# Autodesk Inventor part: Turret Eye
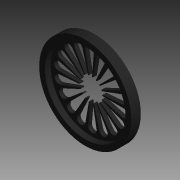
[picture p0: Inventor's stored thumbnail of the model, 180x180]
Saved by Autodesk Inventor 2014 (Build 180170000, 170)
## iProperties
Created: 2013-09
Part Number: Turret Eye
Material: Generic
Document SubType Name: Modeling
Designer: Joey Mason
Appearance: Black
Author: Joey Mason
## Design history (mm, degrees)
sketch "Sketch10"
  geometry: L1 (7.62, 0)-(21.577, 0); L2 (7.36, -1.972)-(20.854, -5.588); L3 (7.16, 2.606)-(20.276, 7.38); L4 (7.591, 0.664)-(21.508, 1.882); L5 (5.837, 4.898)-(16.529, 13.87); L6 (6.906, 3.22)-(19.567, 9.124); L7 (3.81, 6.599)-(10.789, 18.687); L8 (5.388, 5.388)-(15.266, 15.266); L9 (1.323, 7.504)-(3.747, 21.25); L10 (3.22, 6.906)-(9.124, 19.567); L11 (-1.323, 7.504)-(-3.747, 21.25); L12 (0.664, 7.591)-(1.882, 21.508); L13 (-3.81, 6.599)-(-10.789, 18.687); L14 (-1.972, 7.36)-(-5.588, 20.854); L15 (-5.837, 4.898)-(-16.529, 13.87); L16 (-4.371, 6.242)-(-12.384, 17.685); L17 (-7.16, 2.606)-(-20.276, 7.38); L18 (-6.242, 4.371)-(-17.685, 12.384); L19 (-7.62, 0)-(-21.577, 0); L20 (-7.36, 1.972)-(-20.854, 5.588); L21 (-7.16, -2.606)-(-20.276, -7.38); L22 (-7.591, -0.664)-(-21.508, -1.882); L23 (-5.837, -4.898)-(-16.529, -13.87); L24 (-6.906, -3.22)-(-19.567, -9.124); L25 (-3.81, -6.599)-(-10.789, -18.687); L26 (-5.388, -5.388)-(-15.266, -15.266); L27 (-1.323, -7.504)-(-3.747, -21.25); L28 (-3.22, -6.906)-(-9.124, -19.567); L29 (1.323, -7.504)-(3.747, -21.25); L30 (-0.664, -7.591)-(-1.882, -21.508); L31 (3.81, -6.599)-(10.789, -18.687); L32 (1.972, -7.36)-(5.588, -20.854); L33 (5.837, -4.898)-(16.529, -13.87); L34 (4.371, -6.242)-(12.384, -17.685); L35 (7.16, -2.606)-(20.276, -7.38); L36 (6.242, -4.371)-(17.685, -12.384); C1 r 30.48 at (0, 0); C2 r 26.67 at (0, 0); A1 r 2.841 centre (21.577, -2.841) between (20.854, -5.588) and (21.577, 0); A2 r 2.841 centre (21.248, 4.711) between (21.508, 1.882) and (20.276, 7.38); A3 r 2.841 centre (18.355, 11.694) between (19.567, 9.124) and (16.529, 13.87); A4 r 2.841 centre (13.249, 17.266) between (15.266, 15.266) and (10.789, 18.687); A5 r 2.841 centre (6.544, 20.756) between (9.124, 19.567) and (3.747, 21.25); A6 r 2.841 centre (-0.949, 21.743) between (1.882, 21.508) and (-3.747, 21.25); A7 r 2.841 centre (-8.329, 20.107) between (-5.588, 20.854) and (-10.789, 18.687); A8 r 2.841 centre (-14.703, 16.046) between (-12.384, 17.685) and (-16.529, 13.87); A9 r 2.841 centre (-19.305, 10.049) between (-17.685, 12.384) and (-20.276, 7.38); A10 r 2.841 centre (-21.577, 2.841) between (-20.854, 5.588) and (-21.577, 0); A11 r 2.841 centre (-21.248, -4.711) between (-21.508, -1.882) and (-20.276, -7.38); A12 r 2.841 centre (-18.355, -11.694) between (-19.567, -9.124) and (-16.529, -13.87); A13 r 2.841 centre (-13.249, -17.266) between (-15.266, -15.266) and (-10.789, -18.687); A14 r 2.841 centre (-6.544, -20.756) between (-9.124, -19.567) and (-3.747, -21.25); A15 r 2.841 centre (0.949, -21.743) between (-1.882, -21.508) and (3.747, -21.25); A16 r 2.841 centre (8.329, -20.107) between (5.588, -20.854) and (10.789, -18.687); A17 r 2.841 centre (14.703, -16.046) between (12.384, -17.685) and (16.529, -13.87); A18 r 2.841 centre (19.305, -10.049) between (17.685, -12.384) and (20.276, -7.38); A19 r 7.62 centre (0, 0) between (-1.323, 7.504) and (-1.972, 7.36); A20 r 7.62 centre (0, 0) between (1.323, 7.504) and (0.664, 7.591); A21 r 7.62 centre (0, 0) between (3.81, 6.599) and (3.22, 6.906); A22 r 7.62 centre (0, 0) between (5.837, 4.898) and (5.388, 5.388); A23 r 7.62 centre (0, 0) between (7.16, 2.606) and (6.906, 3.22); A24 r 7.62 centre (0, 0) between (7.62, 0) and (7.591, 0.664); A25 r 7.62 centre (0, 0) between (7.16, -2.606) and (7.36, -1.972); A26 r 7.62 centre (0, 0) between (5.837, -4.898) and (6.242, -4.371); A27 r 7.62 centre (0, 0) between (3.81, -6.599) and (4.371, -6.242); A28 r 7.62 centre (0, 0) between (1.323, -7.504) and (1.972, -7.36); A29 r 7.62 centre (0, 0) between (-1.323, -7.504) and (-0.664, -7.591); A30 r 7.62 centre (0, 0) between (-3.81, -6.599) and (-3.22, -6.906); A31 r 7.62 centre (0, 0) between (-5.837, -4.898) and (-5.388, -5.388); A32 r 7.62 centre (0, 0) between (-7.16, -2.606) and (-6.906, -3.22); A33 r 7.62 centre (0, 0) between (-7.62, 0) and (-7.591, -0.664); A34 r 7.62 centre (0, 0) between (-7.16, 2.606) and (-7.36, 1.972); A35 r 7.62 centre (0, 0) between (-3.81, 6.599) and (-4.371, 6.242); A36 r 7.62 centre (0, 0) between (-5.837, 4.898) and (-6.242, 4.371)
  constraints: 72 end point, 72 point on circle, 38 centre point, 2 coincident, 1 tangent, 145 other
  dimensions: "d63" = 360 deg dimension on C1.centre L1.start (derived)
extrude "Extrusion1" new body sketch "Sketch10" distance "d65" = 2.54; taper "d66" = 0 deg
extrude "Extrusion2" join sketch "Sketch10" distance "d67" = 6.35; taper "d68" = 0 deg
sketch "Sketch11"
  geometry: L1 (0, 0)-(0, 30.48); L2 (0, 0)-(0, -30.48); A1 r 30.48 centre (0, 0) between (0, 30.48) and (0, -30.48) reference; 1 further point
  constraints: 4 end point, 2 point on circle, 1 collinear, 1 vertical
body "Solid1"
